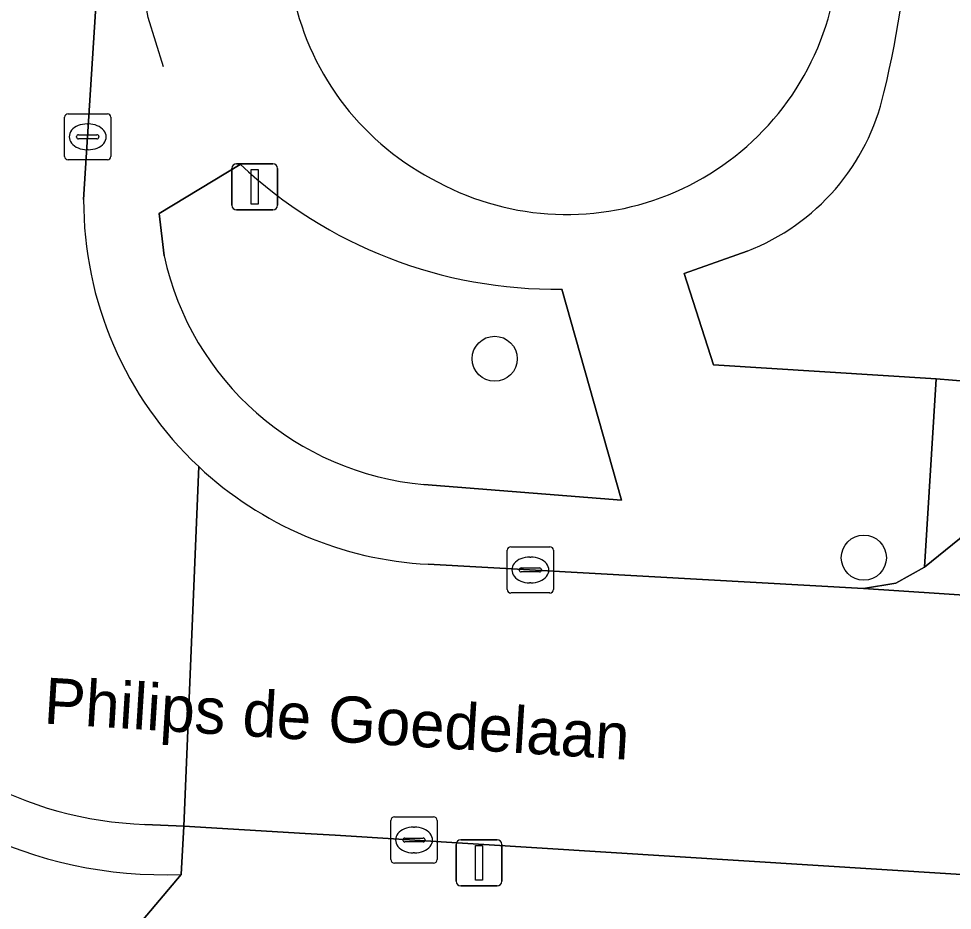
# Model space of a CAD drawing. Extents: x 160102 to 160934, y 382045 to 382923.
# Drawn here: x 160559.57 to 160579.82, y 382504.65 to 382524 of the extents above; entities that cross this region are included whole.
import ezdxf

# ---------------------------------------------------------------- set-up
doc = ezdxf.new("R2010")
doc.units = 0
for name, color, linetype in [('IMGEO_Boom', 7, 'Continuous'), ('IMGEO_Groenvoorziening', 7, 'Continuous'), ('IMGEO_Hek', 7, 'Continuous'), ('IMGEO_Kolk', 7, 'Continuous'), ('IMGEO_Lichtmast', 7, 'Continuous'), ('IMGEO_Openbare_ruimte_label', 7, 'Continuous'), ('IMGEO_Parkeervlak_open', 7, 'Continuous'), ('IMGEO_Rijbaan_lokaal_open', 7, 'Continuous'), ('IMGEO_Terreindeel_zand', 7, 'Continuous'), ('IMGEO_Voetpad_open', 7, 'Continuous')]:
    doc.layers.add(name, color=color, linetype=linetype)

msp = doc.modelspace()

# ---------------------------------------------------------------- linework, layer by layer
at = {"layer": 'IMGEO_Boom'}
for centre in [(160569.896, 382516.619), (160577.902, 382512.304)]:
    msp.add_circle(centre, 0.489, dxfattribs=at)
at = {"layer": 'IMGEO_Groenvoorziening'}
for points in [[(160575.371, 382518.955), (160574.005, 382518.469), (160574.643, 382516.487), (160579.471, 382516.183), (160580.178, 382516.126), (160581.423, 382538.059), (160581.6, 382541.063), (160566.75, 382541.876), (160566.721, 382541.052), (160567.317, 382539.292), (160567.237, 382536.479), (160570.662, 382537.201), (160572.125, 382537.267), (160573.58, 382537.097)], [(160564.375, 382520.836), (160562.621, 382519.768), (160562.725, 382518.851)], [(160568.361, 382513.894), (160572.643, 382513.553), (160571.355, 382518.128)]]:
    msp.add_lwpolyline(points, dxfattribs=at)
for centre, radius, start, end in [((160557.22, 382527.49), 21.725, 346.4218, 8.1648), ((160573.632, 382523.456), 4.826, 291.1234, 347.2222), ((160571.223, 382528.138), 10.01, 226.8356, 270.7553), ((160568.914, 382520.205), 6.336, 192.3436, 264.9916)]:
    msp.add_arc(centre, radius, start, end, dxfattribs=at)
at = {"layer": 'IMGEO_Hek'}
msp.add_lwpolyline([(160562.715, 382522.952), (160562.379, 382524.021), (160562.241, 382524.794), (160562.21, 382526.361), (160562.864, 382536.433)], dxfattribs=at)
at = {"layer": 'IMGEO_Kolk'}
for p, q in [((160560.568, 382521.007), (160560.568, 382521.859)), ((160560.643, 382521.933), (160561.495, 382521.933)), ((160561.569, 382521.859), (160561.569, 382521.007)), ((160561.056, 382521.713), (160561.081, 382521.713)), ((160560.827, 382521.427), (160560.827, 382521.439)), ((160561.265, 382521.39), (160560.867, 382521.39)), ((160560.87, 382521.476), (160561.268, 382521.476)), ((160561.311, 382521.439), (160561.311, 382521.427)), ((160561.079, 382521.153), (160561.054, 382521.153)), ((160561.495, 382520.933), (160560.643, 382520.933)), ((160570.168, 382511.612), (160570.168, 382512.464)), ((160570.243, 382512.538), (160571.095, 382512.538)), ((160571.169, 382512.464), (160571.169, 382511.612)), ((160570.656, 382512.318), (160570.681, 382512.318)), ((160570.427, 382512.032), (160570.427, 382512.044)), ((160570.47, 382512.081), (160570.868, 382512.081)), ((160570.911, 382512.044), (160570.911, 382512.032)), ((160570.865, 382511.995), (160570.467, 382511.995)), ((160570.679, 382511.758), (160570.654, 382511.758)), ((160571.095, 382511.538), (160570.243, 382511.538)), ((160567.645, 382505.754), (160567.645, 382506.606)), ((160567.72, 382506.68), (160568.572, 382506.68)), ((160568.646, 382506.606), (160568.646, 382505.754)), ((160568.133, 382506.46), (160568.158, 382506.46)), ((160567.904, 382506.174), (160567.904, 382506.186)), ((160567.947, 382506.223), (160568.345, 382506.223)), ((160568.388, 382506.186), (160568.388, 382506.174)), ((160568.342, 382506.137), (160567.944, 382506.137)), ((160568.156, 382505.9), (160568.131, 382505.9)), ((160568.572, 382505.68), (160567.72, 382505.68))]:
    msp.add_line(p, q, dxfattribs=at)
for points in [[(160560.568, 382521.007), (160560.568, 382521.859)], [(160560.643, 382521.933), (160561.495, 382521.933)], [(160561.569, 382521.859), (160561.569, 382521.007)], [(160561.495, 382520.933), (160560.643, 382520.933)], [(160570.168, 382511.612), (160570.168, 382512.464)], [(160570.243, 382512.538), (160571.095, 382512.538)], [(160571.169, 382512.464), (160571.169, 382511.612)], [(160571.095, 382511.538), (160570.243, 382511.538)], [(160567.645, 382505.754), (160567.645, 382506.606)], [(160567.72, 382506.68), (160568.572, 382506.68)], [(160568.646, 382506.606), (160568.646, 382505.754)], [(160568.572, 382505.68), (160567.72, 382505.68)]]:
    msp.add_lwpolyline(points, dxfattribs=at)
for centre, radius, start, end in [((160560.645, 382521.857), 0.0765, 91.552, 178.448), ((160560.645, 382521.857), 0.0765, 91.552, 178.448), ((160561.493, 382521.857), 0.0765, 1.552, 88.448), ((160561.493, 382521.857), 0.0765, 1.552, 88.448), ((160560.867, 382521.436), 0.0403, 85.8775, 175.7526), ((160560.864, 382521.426), 0.0366, 178.938, 274.7102), ((160561.268, 382521.433), 0.043, 264.8664, 352.4533), ((160561.272, 382521.438), 0.0386, 1.7309, 96.639), ((160560.645, 382521.009), 0.0765, 181.552, 268.448), ((160560.645, 382521.009), 0.0765, 181.552, 268.448), ((160561.493, 382521.009), 0.0765, 271.552, 358.448), ((160561.493, 382521.009), 0.0765, 271.552, 358.448), ((160570.245, 382512.462), 0.0765, 91.552, 178.448), ((160570.245, 382512.462), 0.0765, 91.552, 178.448), ((160571.093, 382512.462), 0.0765, 1.552, 88.448), ((160571.093, 382512.462), 0.0765, 1.552, 88.448), ((160570.467, 382512.041), 0.0403, 85.8775, 175.7526), ((160570.872, 382512.043), 0.0386, 1.7309, 96.639), ((160570.464, 382512.031), 0.0366, 178.938, 274.7102), ((160570.868, 382512.038), 0.043, 264.8664, 352.4533), ((160570.245, 382511.614), 0.0765, 181.552, 268.448), ((160570.245, 382511.614), 0.0765, 181.552, 268.448), ((160571.093, 382511.614), 0.0765, 271.552, 358.448), ((160571.093, 382511.614), 0.0765, 271.552, 358.448), ((160567.722, 382506.604), 0.0765, 91.552, 178.448), ((160567.722, 382506.604), 0.0765, 91.552, 178.448), ((160568.57, 382506.604), 0.0765, 1.552, 88.448), ((160568.57, 382506.604), 0.0765, 1.552, 88.448), ((160567.944, 382506.183), 0.0403, 85.8775, 175.7526), ((160567.941, 382506.173), 0.0366, 178.938, 274.7102), ((160568.345, 382506.18), 0.043, 264.8664, 352.4533), ((160568.349, 382506.185), 0.0386, 1.7309, 96.639), ((160567.722, 382505.756), 0.0765, 181.552, 268.448), ((160567.722, 382505.756), 0.0765, 181.552, 268.448), ((160568.57, 382505.756), 0.0765, 271.552, 358.448), ((160568.57, 382505.756), 0.0765, 271.552, 358.448)]:
    msp.add_arc(centre, radius, start, end, dxfattribs=at)
for centre, major_axis, ratio, start_param, end_param in [((160561.055, 382521.433), (-0.387, 0.002), 0.722429, 4.712389, 7.853982), ((160561.08, 382521.433), (-0.39, 0.002), 0.717154, 1.570796, 4.712389), ((160570.655, 382512.038), (-0.387, 0.002), 0.722429, 4.712389, 7.853982), ((160570.68, 382512.038), (-0.39, 0.002), 0.717154, 1.570796, 4.712389), ((160568.132, 382506.18), (-0.387, 0.002), 0.722429, 4.712389, 7.853982), ((160568.157, 382506.18), (-0.39, 0.002), 0.717154, 1.570796, 4.712389)]:
    msp.add_ellipse(centre, major_axis=major_axis, ratio=ratio, start_param=start_param, end_param=end_param, dxfattribs=at)
at = {"layer": 'IMGEO_Lichtmast'}
for p, q in [((160564.196, 382519.948), (160564.196, 382520.748)), ((160564.196, 382520.748), (160564.196, 382519.948)), ((160564.296, 382520.848), (160565.086, 382520.848)), ((160565.086, 382520.848), (160564.296, 382520.848)), ((160565.186, 382520.748), (160565.186, 382519.948)), ((160565.186, 382519.948), (160565.186, 382520.748)), ((160565.086, 382519.848), (160564.296, 382519.848)), ((160564.296, 382519.848), (160565.086, 382519.848)), ((160569.158, 382506.185), (160569.948, 382506.185)), ((160569.948, 382506.185), (160569.158, 382506.185)), ((160569.058, 382505.285), (160569.058, 382506.085)), ((160569.058, 382506.085), (160569.058, 382505.285)), ((160570.048, 382506.085), (160570.048, 382505.285)), ((160570.048, 382505.285), (160570.048, 382506.085)), ((160569.948, 382505.185), (160569.158, 382505.185)), ((160569.158, 382505.185), (160569.948, 382505.185))]:
    msp.add_line(p, q, dxfattribs=at)
for points in [[(160564.616, 382520.723), (160564.766, 382520.723), (160564.766, 382519.973), (160564.616, 382519.973), (160564.616, 382520.723)], [(160569.478, 382506.06), (160569.628, 382506.06), (160569.628, 382505.31), (160569.478, 382505.31), (160569.478, 382506.06)]]:
    msp.add_lwpolyline(points, dxfattribs=at)
for centre, start, end in [((160564.296, 382520.748), 90, 180), ((160564.296, 382520.748), 90, 180), ((160565.086, 382520.748), 0, 90), ((160565.086, 382520.748), 360, 90), ((160564.296, 382519.948), 180, 270), ((160564.296, 382519.948), 180, 270), ((160565.086, 382519.948), 270, 0), ((160565.086, 382519.948), 270, 0), ((160569.158, 382506.085), 90, 180), ((160569.158, 382506.085), 90, 180), ((160569.948, 382506.085), 0, 90), ((160569.948, 382506.085), 360, 90), ((160569.158, 382505.285), 180, 270), ((160569.158, 382505.285), 180, 270), ((160569.948, 382505.285), 270, 0), ((160569.948, 382505.285), 270, 0)]:
    msp.add_arc(centre, 0.1, start, end, dxfattribs=at)
at = {"layer": 'IMGEO_Parkeervlak_open'}
msp.add_lwpolyline([(160580.281, 382512.958), (160579.22, 382512.098), (160578.597, 382511.751), (160577.894, 382511.634), (160584.675, 382511.189), (160590.083, 382510.861)], dxfattribs=at)
at = {"layer": 'IMGEO_Rijbaan_lokaal_open'}
for points in [[(160560.981, 382520.071), (160562.086, 382537.415), (160556.099, 382537.796), (160555.566, 382529.462), (160554.615, 382514.878)], [(160562.307, 382506.519), (160563.153, 382506.477), (160563.476, 382514.28)], [(160563.476, 382514.28), (160563.153, 382506.477), (160565.784, 382506.322), (160566.433, 382506.284), (160584.166, 382505.171), (160589.932, 382504.817)], [(160590.083, 382510.861), (160584.675, 382511.189), (160577.894, 382511.634), (160568.451, 382512.161)]]:
    msp.add_lwpolyline(points, dxfattribs=at)
for centre, radius, start, end in [((160568.877, 382520.04), 7.896, 179.7755, 226.8412), ((160568.867, 382520.038), 7.888, 226.8849, 266.9739), ((160562.563, 382514.541), 8.026, 213.8343, 268.175)]:
    msp.add_arc(centre, radius, start, end, dxfattribs=at)
at = {"layer": 'IMGEO_Terreindeel_zand'}
for centre, radius, start, end in [((160571.154, 382525.712), 6.215, 343.9695, 67.4324), ((160571.29, 382525.728), 5.891, 139.2073, 241.9525), ((160571.455, 382525.66), 5.911, 240.2342, 343.6461)]:
    msp.add_arc(centre, radius, start, end, dxfattribs=at)
at = {"layer": 'IMGEO_Voetpad_open'}
for points in [[(160562.258, 382540.108), (160562.086, 382537.415), (160560.981, 382520.071)], [(160562.725, 382518.851), (160562.621, 382519.768), (160564.375, 382520.836)], [(160568.451, 382512.161), (160577.894, 382511.634), (160578.597, 382511.751), (160579.22, 382512.098), (160579.471, 382516.183), (160574.643, 382516.487), (160574.005, 382518.469), (160575.371, 382518.955)], [(160571.355, 382518.128), (160572.643, 382513.553), (160568.361, 382513.894)], [(160600.569, 382511.579), (160597.213, 382513.675), (160594.93, 382515.078), (160580.171, 382515.999), (160580.178, 382516.126), (160579.471, 382516.183), (160579.22, 382512.098), (160580.281, 382512.958)], [(160589.932, 382504.817), (160584.166, 382505.171), (160566.433, 382506.284), (160565.784, 382506.322), (160563.153, 382506.477), (160563.096, 382505.433), (160561.879, 382503.99), (160565.683, 382503.748), (160588.519, 382502.294), (160592.202, 382500), (160636.83, 382472.17), (160638.41, 382471.185), (160643.528, 382467.993), (160652.296, 382462.502), (160664.677, 382454.86), (160665.564, 382456.069), (160673.613, 382450.877), (160675.151, 382453.489), (160672.822, 382454.976), (160671.139, 382456.041), (160667.848, 382458.021)], [(160563.096, 382505.433), (160563.153, 382506.477), (160562.307, 382506.519)], [(160556.719, 382502.436), (160556.747, 382503.435), (160561.16, 382503.138), (160561.879, 382503.99), (160563.096, 382505.433)]]:
    msp.add_lwpolyline(points, dxfattribs=at)
for centre, radius, start, end in [((160571.154, 382525.712), 6.215, 343.9695, 67.4324), ((160557.22, 382527.49), 21.725, 346.4218, 8.1648), ((160571.29, 382525.728), 5.891, 139.2073, 241.9525), ((160571.455, 382525.66), 5.911, 240.2342, 343.6461), ((160573.632, 382523.456), 4.826, 291.1234, 347.2222), ((160571.223, 382528.138), 10.01, 226.8356, 270.7553), ((160568.877, 382520.04), 7.896, 179.7755, 226.8412), ((160568.914, 382520.205), 6.336, 192.3436, 264.9916), ((160568.867, 382520.038), 7.888, 226.8849, 266.9739), ((160562.563, 382514.541), 8.026, 213.8343, 268.175), ((160562.714, 382514.713), 9.287, 214.7481, 272.3566), ((160562.714, 382514.713), 9.287, 214.7481, 272.3566)]:
    msp.add_arc(centre, radius, start, end, dxfattribs=at)

# ---------------------------------------------------------------- texts
at = {"layer": 'IMGEO_Openbare_ruimte_label'}
msp.add_text('Philips de Goedelaan', height=1, rotation=356.4451, dxfattribs=at).set_placement((160560.101, 382508.708))

doc.saveas('drawing.dxf')
